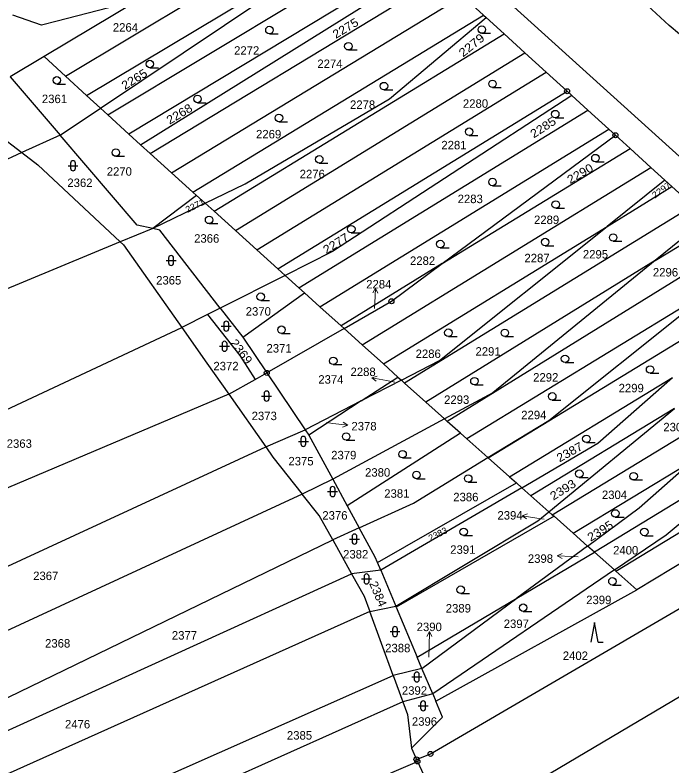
# Model space of a CAD drawing. Extents: x -606517 to -602431, y -1183120 to -1179397.
# Drawn here: x -605022.9 to -604891, y -1180857.3 to -1180706.6 of the extents above; entities that cross this region are included whole.
import ezdxf

# ---------------------------------------------------------------- set-up
doc = ezdxf.new("R2010")
doc.units = 0
doc.header["$LTSCALE"] = 0.68
for name, color, linetype, lineweight in [('1', 7, 'Continuous', 25), ('3', 7, 'Continuous', 25), ('7', 7, 'Continuous', 13), ('8', 7, 'Continuous', 25)]:
    doc.layers.add(name, color=color, linetype=linetype, lineweight=lineweight)
doc.layers.add('2', color=7, linetype='Continuous')

msp = doc.modelspace()

# ---------------------------------------------------------------- linework, layer by layer
at = {"layer": '1'}
for p, q in [((-604956.42, -1180674.5), (-604836.32, -1180783.1)), ((-605012.78, -1180718.85), (-604954.27, -1180683.85)), ((-604891.57, -1180708.68), (-604916.47, -1180685.7)), ((-605008.53, -1180722.74), (-604949.95, -1180687.67)), ((-605005.73, -1180725.3), (-604949.79, -1180687.81)), ((-605004.28, -1180726.64), (-604945.7, -1180691.42)), ((-604941.48, -1180695.14), (-605000.04, -1180730.53)), ((-604997.71, -1180732.67), (-604939.85, -1180696.59)), ((-604995.77, -1180734.41), (-604937.27, -1180698.93)), ((-604991.49, -1180738.27), (-604933.06, -1180702.76)), ((-604933.06, -1180702.76), (-604928.82, -1180706.62)), ((-604998.1, -1180703.65), (-605017.03, -1180714.95)), ((-604998.1, -1180703.65), (-605014.41, -1180707.84)), ((-605017.56, -1180708.65), (-605023.32, -1180706.64)), ((-605014.41, -1180707.84), (-605017.56, -1180708.65)), ((-604987.21, -1180742.12), (-604928.82, -1180706.62)), ((-604947.68, -1180723.44), (-604928.3, -1180707.09)), ((-604928.82, -1180706.62), (-604928.3, -1180707.09)), ((-604928.3, -1180707.09), (-604924.69, -1180710.38)), ((-604851.37, -1180742.57), (-604891.57, -1180708.68)), ((-604982.93, -1180745.99), (-604924.69, -1180710.38)), ((-605017.03, -1180714.95), (-605023.9, -1180718.99)), ((-605012.78, -1180718.85), (-605017.03, -1180714.95)), ((-604978.65, -1180749.84), (-604920.52, -1180714.18)), ((-604974.37, -1180753.7), (-604916.25, -1180718.06)), ((-604916.25, -1180718.06), (-604912.05, -1180721.89)), ((-605023.9, -1180718.99), (-605013.83, -1180730.73)), ((-605008.53, -1180722.74), (-605012.78, -1180718.85)), ((-605036.05, -1180723.03), (-605021.53, -1180734.2)), ((-605005.73, -1180725.3), (-605008.53, -1180722.74)), ((-604970.13, -1180757.51), (-604912.05, -1180721.89)), ((-604911.13, -1180722.73), (-604959.16, -1180754.07)), ((-604912.05, -1180721.89), (-604911.13, -1180722.73)), ((-604907.9, -1180725.66), (-604911.13, -1180722.73)), ((-604976.69, -1180740.5), (-604947.68, -1180723.44)), ((-605013.83, -1180730.73), (-605005.73, -1180725.3)), ((-605005.73, -1180725.3), (-605004.28, -1180726.64)), ((-604965.9, -1180761.33), (-604907.9, -1180725.66)), ((-604903.66, -1180729.52), (-604907.9, -1180725.66)), ((-605004.28, -1180726.64), (-605000.04, -1180730.53)), ((-605000.04, -1180730.53), (-604997.71, -1180732.67)), ((-604961.69, -1180765.13), (-604903.66, -1180729.52)), ((-604903.66, -1180729.52), (-604902.35, -1180730.72)), ((-605013.83, -1180730.73), (-605021.53, -1180734.2)), ((-604998.4, -1180748.74), (-605013.83, -1180730.73)), ((-604937.12, -1180756.48), (-604902.35, -1180730.72)), ((-604902.35, -1180730.72), (-604899.42, -1180733.38)), ((-604997.71, -1180732.67), (-604995.77, -1180734.41)), ((-604937.12, -1180756.48), (-604899.42, -1180733.38)), ((-604899.42, -1180733.38), (-604895.23, -1180737.2)), ((-605021.53, -1180734.2), (-605125.99, -1180781.59)), ((-605021.53, -1180734.2), (-605018.32, -1180736.67)), ((-604995.77, -1180734.41), (-604991.49, -1180738.27)), ((-605018.32, -1180736.67), (-605001.77, -1180752.1)), ((-604953.22, -1180772.76), (-604895.23, -1180737.2)), ((-604895.23, -1180737.2), (-604892.42, -1180739.76)), ((-604991.49, -1180738.27), (-604987.21, -1180742.12)), ((-604984.72, -1180744.37), (-604976.69, -1180740.5)), ((-604892.42, -1180739.76), (-604903.99, -1180749.02)), ((-604903.99, -1180749.02), (-604891.02, -1180741.04)), ((-604891.02, -1180741.04), (-604892.42, -1180739.76)), ((-604891.02, -1180741.04), (-604886.8, -1180744.87)), ((-604987.21, -1180742.12), (-604986.47, -1180742.79)), ((-604986.47, -1180742.79), (-604995.24, -1180749.46)), ((-604984.72, -1180744.37), (-604986.47, -1180742.79)), ((-604984.72, -1180744.37), (-604995.24, -1180749.46)), ((-604982.93, -1180745.99), (-604984.72, -1180744.37)), ((-604886.8, -1180744.87), (-604944.67, -1180780.46)), ((-604978.65, -1180749.84), (-604982.93, -1180745.99)), ((-604884, -1180747.45), (-604894.34, -1180755.88)), ((-604894.34, -1180755.88), (-604882.66, -1180748.67)), ((-604995.24, -1180749.46), (-605001.77, -1180752.1)), ((-604995.24, -1180749.46), (-604998.4, -1180748.74)), ((-604993.83, -1180749.78), (-604995.24, -1180749.46)), ((-604981.71, -1180765.42), (-604993.83, -1180749.78)), ((-604974.37, -1180753.7), (-604978.65, -1180749.84)), ((-604948.94, -1180776.61), (-604903.99, -1180749.02)), ((-604937.66, -1180775.95), (-604903.99, -1180749.02)), ((-605001.77, -1180752.1), (-605114.95, -1180799.05)), ((-605001.77, -1180752.1), (-605001.14, -1180752.69)), ((-604878.42, -1180752.5), (-604936.12, -1180788.17)), ((-604970.13, -1180757.51), (-604974.37, -1180753.7)), ((-604959.16, -1180754.07), (-604968.66, -1180758.85)), ((-604894.34, -1180755.88), (-604940.4, -1180784.31)), ((-604894.34, -1180755.88), (-604926.94, -1180782.41)), ((-604968.66, -1180758.85), (-604970.13, -1180757.51)), ((-604937.12, -1180756.48), (-604957.45, -1180768.94)), ((-604947.32, -1180764.04), (-604937.12, -1180756.48)), ((-604968.66, -1180758.85), (-604981.71, -1180765.42)), ((-604968.66, -1180758.85), (-604965.9, -1180761.33)), ((-604927.91, -1180795.45), (-604870.12, -1180760.18)), ((-604965.9, -1180761.33), (-604964.79, -1180762.33)), ((-604882.04, -1180761.04), (-604932.19, -1180791.66)), ((-604915.74, -1180787.95), (-604882.04, -1180761.04)), ((-604977.18, -1180771.26), (-604964.79, -1180762.33)), ((-604964.79, -1180762.33), (-604961.69, -1180765.13)), ((-604957.45, -1180768.94), (-604961.69, -1180765.13)), ((-604956.83, -1180769.5), (-604947.32, -1180764.04)), ((-604984.23, -1180766.69), (-604989.4, -1180769.3)), ((-604981.71, -1180765.42), (-604984.23, -1180766.69)), ((-604984.23, -1180766.69), (-604977.77, -1180774.94)), ((-604981.71, -1180765.42), (-604977.18, -1180771.26)), ((-604956.83, -1180769.5), (-604972.35, -1180778.41)), ((-604956.83, -1180769.5), (-604957.45, -1180768.94)), ((-604953.22, -1180772.76), (-604956.83, -1180769.5)), ((-604977.18, -1180771.26), (-604972.35, -1180778.41)), ((-604948.94, -1180776.61), (-604953.22, -1180772.76)), ((-604977.77, -1180774.94), (-604974.69, -1180779.75)), ((-604984.36, -1180776.43), (-604979.97, -1180782.7)), ((-604946.03, -1180779.24), (-604948.94, -1180776.61)), ((-604945.31, -1180779.89), (-604937.66, -1180775.95)), ((-604915.04, -1180806.88), (-604864.13, -1180775.9)), ((-604974.69, -1180779.75), (-604972.35, -1180778.41)), ((-604972.35, -1180778.41), (-604964.62, -1180789.82)), ((-604979.97, -1180782.7), (-604974.69, -1180779.75)), ((-604953.37, -1180784.03), (-604946.03, -1180779.24)), ((-604945.31, -1180779.89), (-604953.37, -1180784.03)), ((-604946.03, -1180779.24), (-604945.31, -1180779.89)), ((-604944.67, -1180780.46), (-604945.31, -1180779.89)), ((-604923.61, -1180799.27), (-604890.89, -1180779.33)), ((-604905.86, -1180792.52), (-604890.89, -1180779.33)), ((-604940.4, -1180784.31), (-604944.67, -1180780.46)), ((-604979.97, -1180782.7), (-605095.11, -1180831.36)), ((-604979.97, -1180782.7), (-604972.56, -1180793.28)), ((-604926.94, -1180782.41), (-604936.69, -1180787.66)), ((-604953.37, -1180784.03), (-604964.62, -1180789.82)), ((-604953.37, -1180784.03), (-604963.89, -1180790.9)), ((-604936.69, -1180787.66), (-604940.4, -1180784.31)), ((-604902.27, -1180818.21), (-604845.03, -1180783.39)), ((-604890.49, -1180785.54), (-604919.31, -1180803.09)), ((-604915.71, -1180806.28), (-604890.49, -1180785.54)), ((-604936.69, -1180787.66), (-604959.09, -1180799.73)), ((-604936.12, -1180788.17), (-604936.69, -1180787.66)), ((-604933.46, -1180790.53), (-604936.12, -1180788.17)), ((-604927.95, -1180795.42), (-604915.74, -1180787.95)), ((-604964.62, -1180789.82), (-604963.89, -1180790.9)), ((-604963.89, -1180790.9), (-604959.09, -1180799.73)), ((-604933.46, -1180790.53), (-604956.18, -1180805.07)), ((-604932.19, -1180791.66), (-604933.46, -1180790.53)), ((-604927.95, -1180795.42), (-604932.19, -1180791.66)), ((-604868.99, -1180791.56), (-604906.57, -1180814.4)), ((-604892.16, -1180810.88), (-604868.99, -1180791.56)), ((-604972.56, -1180793.28), (-604971.14, -1180795.31)), ((-604921.15, -1180801.46), (-604905.86, -1180792.52)), ((-604971.14, -1180795.31), (-604965.22, -1180802.77)), ((-604942.9, -1180804.56), (-604927.95, -1180795.42)), ((-604927.95, -1180795.42), (-604927.91, -1180795.45)), ((-604852.8, -1180794.67), (-604898.08, -1180821.93)), ((-604927.91, -1180795.45), (-604923.61, -1180799.27)), ((-604910.85, -1180810.59), (-604887.16, -1180796.25)), ((-604897.57, -1180805.46), (-604887.16, -1180796.25)), ((-604959.09, -1180799.73), (-604965.22, -1180802.77)), ((-604959.09, -1180799.73), (-604956.18, -1180805.07)), ((-604923.61, -1180799.27), (-604922.24, -1180800.49)), ((-604950.12, -1180816.46), (-604922.24, -1180800.49)), ((-604921.15, -1180801.46), (-604949.47, -1180818)), ((-604922.24, -1180800.49), (-604921.15, -1180801.46)), ((-604919.31, -1180803.09), (-604921.15, -1180801.46)), ((-604965.22, -1180802.77), (-605081.76, -1180856.63)), ((-604961.86, -1180807.01), (-604965.22, -1180802.77)), ((-604915.71, -1180806.28), (-604919.31, -1180803.09)), ((-604956.18, -1180805.07), (-604953.77, -1180809.5)), ((-604953.77, -1180809.5), (-604942.9, -1180804.56)), ((-604907.97, -1180813.15), (-604897.57, -1180805.46)), ((-604959.12, -1180811.92), (-604961.86, -1180807.01)), ((-604914.68, -1180807.19), (-604946.35, -1180825.44)), ((-604917.95, -1180808.13), (-604915.71, -1180806.28)), ((-604915.71, -1180806.28), (-604915.04, -1180806.88)), ((-604915.04, -1180806.88), (-604914.68, -1180807.19)), ((-604910.85, -1180810.59), (-604914.68, -1180807.19)), ((-604946.46, -1180825.19), (-604917.95, -1180808.13)), ((-604953.77, -1180809.5), (-604959.12, -1180811.92)), ((-604950.57, -1180815.37), (-604953.77, -1180809.5)), ((-605076.11, -1180868.57), (-604959.12, -1180811.92)), ((-604959.12, -1180811.92), (-604955.31, -1180818.73)), ((-604907.97, -1180813.15), (-604910.85, -1180810.59)), ((-604902.55, -1180817.96), (-604892.16, -1180810.88)), ((-604907.97, -1180813.15), (-604922.17, -1180823.64)), ((-604922.17, -1180823.64), (-604906.57, -1180814.4)), ((-604950.12, -1180816.46), (-604950.57, -1180815.37)), ((-604949.47, -1180818), (-604950.12, -1180816.46)), ((-604949.47, -1180818), (-604955.31, -1180818.73)), ((-604949.47, -1180818), (-604946.46, -1180825.19)), ((-604902.55, -1180817.96), (-604939.03, -1180842.82)), ((-604902.27, -1180818.21), (-604902.55, -1180817.96)), ((-605074.12, -1180872.77), (-604955.31, -1180818.73)), ((-604955.31, -1180818.73), (-604952.81, -1180823.2)), ((-604939.48, -1180854.86), (-604878.67, -1180819.33)), ((-604898.08, -1180821.93), (-604902.27, -1180818.21)), ((-604938.42, -1180844.27), (-604898.08, -1180821.93)), ((-604952.81, -1180823.2), (-604951.69, -1180826.26)), ((-604942.13, -1180835.47), (-604922.17, -1180823.64)), ((-604941.19, -1180837.7), (-604922.17, -1180823.64)), ((-604951.69, -1180826.26), (-604946.46, -1180825.19)), ((-604946.35, -1180825.44), (-604946.46, -1180825.19)), ((-604946.35, -1180825.44), (-604942.13, -1180835.47)), ((-604951.69, -1180826.26), (-605071.22, -1180879.91)), ((-604946.99, -1180839.11), (-604951.69, -1180826.26)), ((-604864.72, -1180828.8), (-604935.53, -1180870.63)), ((-604941.19, -1180837.7), (-604942.13, -1180835.47)), ((-605066.61, -1180892.1), (-604946.99, -1180839.11)), ((-604941.19, -1180837.7), (-604946.99, -1180839.11)), ((-604946.99, -1180839.11), (-604945.04, -1180844.43)), ((-604939.03, -1180842.82), (-604941.19, -1180837.7)), ((-604939.03, -1180842.82), (-604945.04, -1180844.43)), ((-604939.03, -1180842.82), (-604938.42, -1180844.27)), ((-604945.04, -1180844.43), (-605064.46, -1180897.79)), ((-604945.04, -1180844.43), (-604944.12, -1180846.95)), ((-604937.07, -1180847.48), (-604938.42, -1180844.27)), ((-604944.12, -1180846.95), (-604943.32, -1180853.74)), ((-604943.32, -1180853.74), (-604937.07, -1180847.48)), ((-604943.32, -1180853.74), (-604942.3, -1180855.97)), ((-604942.3, -1180855.97), (-604939.48, -1180854.86)), ((-605061.96, -1180907.49), (-604942.1, -1180856.39)), ((-604942.1, -1180856.39), (-604942.3, -1180855.97)), ((-604942.1, -1180856.39), (-604935.53, -1180870.63))]:
    msp.add_line(p, q, dxfattribs=at)
for points in [[(-604924.69, -1180710.38), (-604920.52, -1180714.18), (-604916.25, -1180718.06)], [(-605001.14, -1180752.69), (-604989.4, -1180769.3), (-604984.36, -1180776.43)], [(-605102.25, -1180819.09), (-605100.85, -1180821.49), (-604989.4, -1180769.3)], [(-605086.77, -1180846.05), (-604972.56, -1180793.28), (-604964.62, -1180789.82)], [(-604902.55, -1180817.96), (-604906.57, -1180814.4), (-604907.97, -1180813.15)]]:
    msp.add_lwpolyline(points, dxfattribs=at)
at = {"layer": '3'}
for p, q in [((-604971.823, -1180710.36), (-604970.073, -1180710.36)), ((-604929.163, -1180710.27), (-604927.413, -1180710.27)), ((-604955.973, -1180713.61), (-604954.223, -1180713.61)), ((-604995.833, -1180717.18), (-604994.083, -1180717.18)), ((-605014.503, -1180720.45), (-605012.753, -1180720.45)), ((-604927.023, -1180721.15), (-604925.273, -1180721.15)), ((-604948.823, -1180721.61), (-604947.073, -1180721.61)), ((-604986.263, -1180724.19), (-604984.513, -1180724.19)), ((-604914.433, -1180727.23), (-604912.683, -1180727.23)), ((-604969.913, -1180728), (-604968.163, -1180728)), ((-604931.723, -1180730.76), (-604929.973, -1180730.76)), ((-605002.663, -1180734.95), (-605000.913, -1180734.95)), ((-605011.761, -1180736.351), (-605011.761, -1180737.352)), ((-605010.759, -1180737.352), (-605010.759, -1180736.351)), ((-604961.823, -1180736.31), (-604960.073, -1180736.31)), ((-604906.363, -1180736.06), (-604904.613, -1180736.06)), ((-605012.261, -1180736.851), (-605010.259, -1180736.851)), ((-604927.043, -1180740.85), (-604925.293, -1180740.85)), ((-604914.343, -1180745.38), (-604912.593, -1180745.38)), ((-604983.933, -1180748.46), (-604982.183, -1180748.46)), ((-604955.383, -1180750.31), (-604953.633, -1180750.31)), ((-604916.463, -1180752.9), (-604914.713, -1180752.9)), ((-604902.813, -1180751.99), (-604901.063, -1180751.99)), ((-604937.513, -1180753.31), (-604935.763, -1180753.31)), ((-604992.571, -1180755.851), (-604990.569, -1180755.851)), ((-604992.071, -1180755.351), (-604992.071, -1180756.352)), ((-604991.069, -1180756.352), (-604991.069, -1180755.351)), ((-604973.573, -1180763.87), (-604971.823, -1180763.87)), ((-604981.491, -1180769.031), (-604979.489, -1180769.031)), ((-604980.991, -1180768.531), (-604980.991, -1180769.532)), ((-604979.989, -1180769.532), (-604979.989, -1180768.531)), ((-604969.403, -1180770.5), (-604967.653, -1180770.5)), ((-604935.893, -1180771.1), (-604934.143, -1180771.1)), ((-604924.563, -1180771.13), (-604922.813, -1180771.13)), ((-604981.341, -1180772.571), (-604981.341, -1180773.572)), ((-604980.339, -1180773.572), (-604980.339, -1180772.571)), ((-604981.841, -1180773.071), (-604979.839, -1180773.071)), ((-604959.003, -1180776.75), (-604957.253, -1180776.75)), ((-604912.473, -1180776.33), (-604910.723, -1180776.33)), ((-604895.393, -1180778.48), (-604893.643, -1180778.48)), ((-604930.663, -1180780.81), (-604928.913, -1180780.81)), ((-604973.391, -1180783.071), (-604971.389, -1180783.071)), ((-604972.891, -1180782.571), (-604972.891, -1180783.572)), ((-604971.889, -1180783.572), (-604971.889, -1180782.571)), ((-604915.033, -1180783.87), (-604913.283, -1180783.87)), ((-604966.011, -1180792.151), (-604964.009, -1180792.151)), ((-604965.511, -1180791.651), (-604965.511, -1180792.652)), ((-604964.509, -1180792.652), (-604964.509, -1180791.651)), ((-604956.413, -1180791.93), (-604954.663, -1180791.93)), ((-604908.183, -1180792.4), (-604906.433, -1180792.4)), ((-604945.083, -1180795.48), (-604943.333, -1180795.48)), ((-604942.293, -1180799.64), (-604940.543, -1180799.64)), ((-604909.603, -1180799.39), (-604907.853, -1180799.39)), ((-604898.693, -1180799.9), (-604896.943, -1180799.9)), ((-604931.903, -1180800.35), (-604930.153, -1180800.35)), ((-604960.141, -1180802.221), (-604958.139, -1180802.221)), ((-604959.641, -1180801.721), (-604959.641, -1180802.722)), ((-604958.639, -1180802.722), (-604958.639, -1180801.721)), ((-604902.373, -1180807.36), (-604900.623, -1180807.36)), ((-604955.741, -1180811.761), (-604953.739, -1180811.761)), ((-604955.241, -1180811.261), (-604955.241, -1180812.262)), ((-604954.239, -1180812.262), (-604954.239, -1180811.261)), ((-604932.823, -1180811.05), (-604931.073, -1180811.05)), ((-604896.543, -1180811.08), (-604894.793, -1180811.08)), ((-604952.821, -1180819.261), (-604952.821, -1180820.262)), ((-604951.819, -1180820.262), (-604951.819, -1180819.261)), ((-604953.321, -1180819.761), (-604951.319, -1180819.761)), ((-604902.953, -1180820.99), (-604901.203, -1180820.99)), ((-604933.413, -1180822.67), (-604931.663, -1180822.67)), ((-604920.873, -1180826.27), (-604919.123, -1180826.27)), ((-604947.111, -1180829.831), (-604947.111, -1180830.832)), ((-604946.109, -1180830.832), (-604946.109, -1180829.831)), ((-604947.611, -1180830.331), (-604945.609, -1180830.331)), ((-604905.79, -1180832.47), (-604904.794, -1180832.47)), ((-604942.731, -1180838.931), (-604942.731, -1180839.932)), ((-604941.729, -1180839.932), (-604941.729, -1180838.931)), ((-604943.231, -1180839.431), (-604941.229, -1180839.431)), ((-604941.461, -1180844.721), (-604941.461, -1180845.722)), ((-604940.459, -1180845.722), (-604940.459, -1180844.721)), ((-604941.961, -1180845.221), (-604939.959, -1180845.221))]:
    msp.add_line(p, q, dxfattribs=at)
msp.add_lwpolyline([(-604905.79, -1180832.47), (-604906.54, -1180828.47), (-604907.29, -1180832.47)], dxfattribs=at)
for centre in [(-604971.8229, -1180709.6098), (-604929.1629, -1180709.5198), (-604955.9729, -1180712.8598), (-604995.8329, -1180716.4298), (-605014.5029, -1180719.6998), (-604927.0229, -1180720.3998), (-604948.8229, -1180720.8598), (-604986.2629, -1180723.4398), (-604914.4329, -1180726.4798), (-604969.9129, -1180727.2498), (-604931.7229, -1180730.0098), (-605002.6629, -1180734.1998), (-604961.8229, -1180735.5598), (-604906.3629, -1180735.3098), (-604927.0429, -1180740.0998), (-604914.3429, -1180744.6298), (-604983.9329, -1180747.7098), (-604955.3829, -1180749.5598), (-604916.4629, -1180752.1498), (-604902.8129, -1180751.2398), (-604937.5129, -1180752.5598), (-604973.5729, -1180763.1198), (-604969.4029, -1180769.7498), (-604935.8929, -1180770.3498), (-604924.5629, -1180770.3798), (-604959.0029, -1180775.9998), (-604912.4729, -1180775.5798), (-604895.3929, -1180777.7298), (-604930.6629, -1180780.0598), (-604915.0329, -1180783.1198), (-604956.4129, -1180791.1798), (-604908.1829, -1180791.6498), (-604945.0829, -1180794.7298), (-604942.2929, -1180798.8898), (-604909.6029, -1180798.6398), (-604898.6929, -1180799.1498), (-604931.9029, -1180799.5998), (-604902.3729, -1180806.6098), (-604932.8229, -1180810.2998), (-604896.5429, -1180810.3298), (-604902.9529, -1180820.2398), (-604933.4129, -1180821.9198), (-604920.8729, -1180825.5198)]:
    msp.add_circle(centre, 0.75, dxfattribs=at)
for centre, start, end in [((-605011.26, -1180736.3509), 0, 180), ((-605011.26, -1180737.3509), 180, 359.98789), ((-604991.57, -1180755.3509), 0, 180), ((-604991.57, -1180756.3509), 180, 359.98789), ((-604980.49, -1180768.5309), 0, 180), ((-604980.49, -1180769.5309), 180, 359.98789), ((-604980.84, -1180772.5709), 0, 180), ((-604980.84, -1180773.5709), 180, 359.98789), ((-604972.39, -1180782.5709), 0, 180), ((-604972.39, -1180783.5709), 180, 359.98789), ((-604965.01, -1180791.6509), 0, 180), ((-604965.01, -1180792.6509), 180, 359.98789), ((-604959.14, -1180801.7209), 0, 180), ((-604959.14, -1180802.7209), 180, 359.98789), ((-604954.74, -1180811.2609), 0, 180), ((-604954.74, -1180812.2609), 180, 359.98789), ((-604952.32, -1180819.2609), 0, 180), ((-604952.32, -1180820.2609), 180, 359.98789), ((-604946.61, -1180829.8309), 0, 180), ((-604946.61, -1180830.8309), 180, 359.98789), ((-604942.23, -1180838.9309), 0, 180), ((-604942.23, -1180839.9309), 180, 359.98789), ((-604940.96, -1180844.7209), 0, 180), ((-604940.96, -1180845.7209), 180, 359.98789)]:
    msp.add_arc(centre, 0.5, start, end, dxfattribs=at)
at = {"layer": '7'}
for p, q in [((-604950.523, -1180761.393), (-604951.075, -1180762.367)), ((-604951.246, -1180779.397), (-604950.358, -1180780.08)), ((-604956.081, -1180788.906), (-604957.014, -1180788.287)), ((-604921.094, -1180807.061), (-604920.183, -1180807.712)), ((-604914.039, -1180815.145), (-604913.056, -1180815.681)), ((-604939.655, -1180830.291), (-604940.191, -1180831.274))]:
    msp.add_line(p, q, dxfattribs=at)
for points in [[(-604950.74, -1180765.47), (-604950.68, -1180764.39), (-604950.523, -1180761.393), (-604950.075, -1180762.419)], [(-604946.63, -1180780.28), (-604948.3, -1180779.97), (-604951.246, -1180779.397), (-604950.167, -1180779.097)], [(-604960.38, -1180788.38), (-604959.06, -1180788.54), (-604956.081, -1180788.906), (-604957.136, -1180789.281)], [(-604916.67, -1180807.75), (-604918.13, -1180807.53), (-604921.094, -1180807.061), (-604920.027, -1180806.723)], [(-604909.8, -1180815.29), (-604911.04, -1180815.25), (-604914.039, -1180815.145), (-604913.021, -1180814.68)], [(-604939.82, -1180835.45), (-604939.76, -1180833.29), (-604939.655, -1180830.291), (-604939.19, -1180831.309)]]:
    msp.add_lwpolyline(points, dxfattribs=at)
at = {"layer": '8'}
for centre, radius in [((-604912.05, -1180721.8899), 0.5), ((-604912.05, -1180721.8899), 0.0303), ((-604902.35, -1180730.7199), 0.5), ((-604902.35, -1180730.7199), 0.0303), ((-604947.32, -1180764.0399), 0.5), ((-604947.32, -1180764.0399), 0.0303), ((-604972.35, -1180778.4099), 0.5), ((-604972.35, -1180778.4099), 0.0303), ((-604942.3, -1180855.9699), 0.5), ((-604939.48, -1180854.8599), 0.5), ((-604939.48, -1180854.8599), 0.0303), ((-604942.1, -1180856.3899), 0.5), ((-604942.3, -1180855.9699), 0.0303), ((-604942.1, -1180856.3899), 0.0303)]:
    msp.add_circle(centre, radius, dxfattribs=at)

# ---------------------------------------------------------------- texts
at = {"layer": '2'}
for s, height, rotation, width, p in [('2275', 1.7, 31, 1.1, (-604958.501, -1180711.404)), ('2279', 1.7, 39, 1.15, (-604932.962, -1180715.14)), ('2265', 1.7, 32, 1.1, (-605000.854, -1180721.67)), ('2268', 1.7, 31, 1.1, (-604991.851, -1180728.604)), ('2285', 1.7, 33, 1.1, (-604918.748, -1180731.376)), ('2290', 1.7, 30, 1.1, (-604911.427, -1180740.548)), ('2297', 1.27, 36, 1.1, (-604894.433, -1180743.446)), ('2271', 1.27, 26, 1.05, (-604988.28, -1180746.305)), ('2277', 1.7, 32, 1.1, (-604960.384, -1180754.63)), ('2369', 1.7, 307, 1.1, (-604979.809, -1180772.415)), ('2387', 1.7, 29, 1.1, (-604913.573, -1180796.391)), ('2393', 1.7, 32, 1.1, (-604914.804, -1180804.05)), ('2395', 1.7, 32, 1.1, (-604907.314, -1180812.31)), ('2383', 1.28, 27, 1.05, (-604939.504, -1180812.245)), ('2384', 1.7, 293, 1.05, (-604951.821, -1180820.656))]:
    msp.add_text(s, height=height, rotation=rotation, dxfattribs=dict(at, width=width)).set_placement(p)
for s, p in [('2264', (-605003.26, -1180709.935)), ('2272', (-604978.92, -1180714.565)), ('2274', (-604962.2, -1180717.235)), ('2361', (-605017.51, -1180724.275)), ('2278', (-604955.64, -1180725.435)), ('2280', (-604932.97, -1180725.215)), ('2269', (-604974.51, -1180731.355)), ('2281', (-604937.3, -1180733.555)), ('2270', (-605004.49, -1180738.845)), ('2276', (-604965.75, -1180739.355)), ('2362', (-605012.4, -1180741.115)), ('2283', (-604934.03, -1180744.345)), ('2289', (-604918.7, -1180748.545)), ('2366', (-604986.94, -1180752.285)), ('2287', (-604920.62, -1180756.215)), ('2295', (-604908.88, -1180755.455)), ('2282', (-604943.6, -1180756.745)), ('2296', (-604894.82, -1180759.065)), ('2365', (-604994.57, -1180760.675)), ('2284', (-604952.39, -1180761.465)), ('2370', (-604976.58, -1180766.925)), ('2371', (-604972.41, -1180774.325)), ('2286', (-604942.47, -1180775.425)), ('2291', (-604930.45, -1180774.955)), ('2372', (-604983.07, -1180777.895)), ('2288', (-604955.54, -1180779.045)), ('2374', (-604962.01, -1180780.575)), ('2292', (-604918.87, -1180780.155)), ('2299', (-604901.71, -1180782.305)), ('2293', (-604936.75, -1180784.635)), ('2373', (-604975.39, -1180787.895)), ('2294', (-604921.26, -1180787.705)), ('2378', (-604955.36, -1180789.955)), ('2303', (-604892.73, -1180790.135)), ('2363', (-605024.57, -1180793.445)), ('2375', (-604968.01, -1180796.975)), ('2379', (-604959.42, -1180795.755)), ('2380', (-604952.62, -1180799.235)), ('2381', (-604948.77, -1180803.465)), ('2386', (-604934.91, -1180804.175)), ('2304', (-604905.06, -1180803.725)), ('2376', (-604961.2, -1180807.855)), ('2394', (-604926.04, -1180807.845)), ('2391', (-604935.52, -1180814.715)), ('2400', (-604902.82, -1180814.845)), ('2382', (-604957.03, -1180815.655)), ('2398', (-604919.93, -1180816.525)), ('2367', (-605019.26, -1180819.985)), ('2399', (-604908.22, -1180824.815)), ('2389', (-604936.42, -1180826.495)), ('2390', (-604942.26, -1180830.225)), ('2397', (-604924.78, -1180829.605)), ('2377', (-604991.41, -1180831.925)), ('2368', (-605016.87, -1180833.525)), ('2388', (-604948.58, -1180834.475)), ('2402', (-604912.92, -1180836.015)), ('2392', (-604945.23, -1180842.995)), ('2476', (-605012.87, -1180849.755)), ('2396', (-604943.22, -1180849.215)), ('2385', (-604968.31, -1180851.995))]:
    msp.add_text(s, height=1.7, dxfattribs=at).set_placement(p)

doc.saveas('drawing.dxf')
